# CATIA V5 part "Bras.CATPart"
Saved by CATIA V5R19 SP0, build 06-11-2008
Part number: Bras
Publications: "L", "La", "e"
Bounding box of the stored display mesh (mm): x -140 to 0, y 0 to 40, z 0 to 10
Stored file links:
  G:\EU_thinkMotion\CFAO_2010\MMS_groupe3\MMS_groupe3\A reprendre\evulliez\evulliez\Bras.CATPart
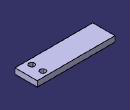
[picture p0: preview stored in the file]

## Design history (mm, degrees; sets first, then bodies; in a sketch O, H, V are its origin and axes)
Parameters
  L = 140 mm
  La = 40 mm
  e = 10 mm
Body1 (main body)
  Sketch1 on yz-plane, origin (0, 0, 0), H (0, 1, 0), V (0, 0, 1)
    line L1 (0, 0) -> (40, 0)
    line L2 (40, 0) -> (40, 10)
    line L3 (40, 10) -> (0, 10)
    line L4 (0, 10) -> (0, 0)
    length L2 = 10 {= e}
    length L1 = 40 {= La}
    horizontal: L1 H, L3 H
    vertical: L2 V, L4 V
  Pad1: profile Sketch1, direction (-1, 0, 0), length 140 {= L}
  Point1: type OnPlane, Support face of Pad1 from Sketch1.L1, H -20, V -10, Direction (1, 0, 0)
  Point2: type OnPlane, Support face of Pad1 from Sketch1.L1, H -20, V -30 {= -(La -10mm)}, Direction (1, 0, 0)
  Sketch2 on face of Pad1 from Sketch1.L1, origin (-10, 30, 0), H (1, 0, 0), V (0, -1, 0)
    point P1 (-10, 0)
    reference projected point E1 (-10, 0) from Point2
    coincidence: E1 P1
  Hole1: placed by Sketch2, at (-20, 30, 0) direction (0, 0, 1), diameter 10, through (limit type 6)
  Sketch3 on face of Pad1 from Sketch1.L1, origin (-10, 10, 0), H (1, 0, 0), V (0, -1, 0)
    point P1 (-10, 0)
    reference projected point E1 (-10, 0) from Point1
    coincidence: E1 P1
  Hole2: placed by Sketch3, at (-20, 10, 0) direction (0, 0, 1), diameter 10, through (limit type 6)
